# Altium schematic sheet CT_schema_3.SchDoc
size 339 x 183 mm
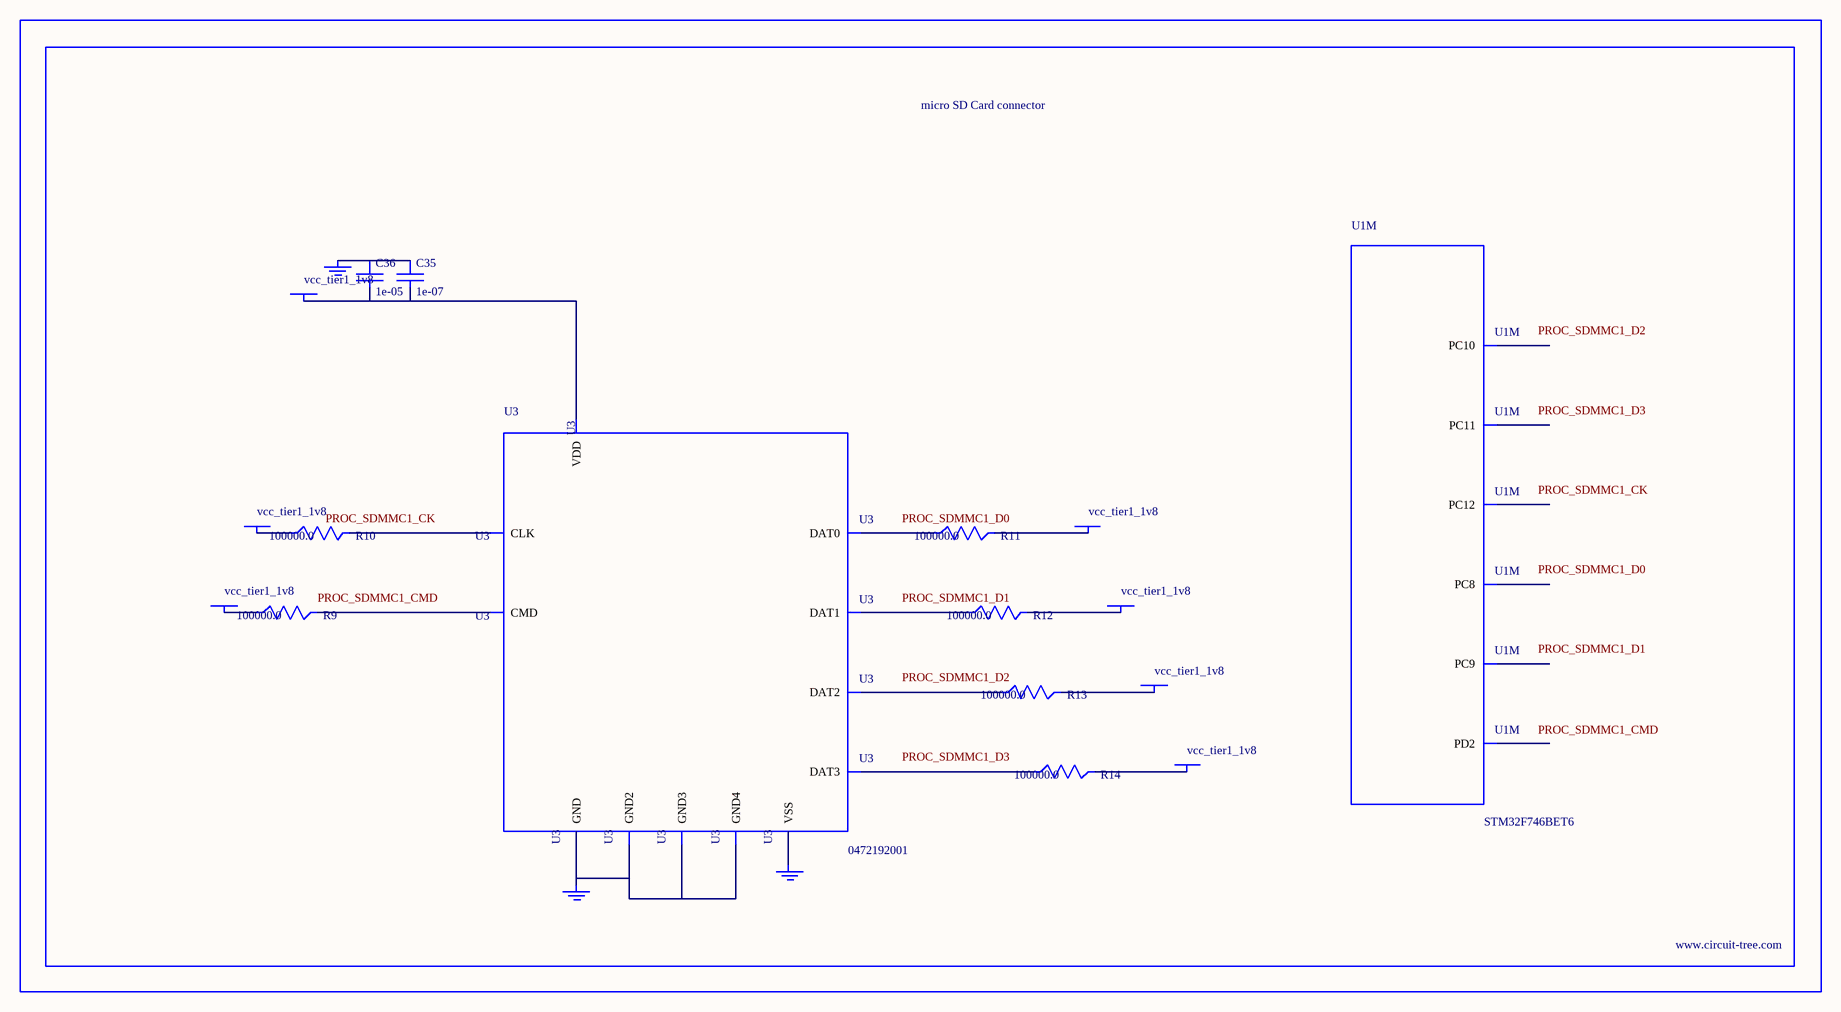
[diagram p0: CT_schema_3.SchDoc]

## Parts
BORDER2  (no value)
C35  1e-07  [C0402]
C36  1e-05  [C0805]
GND_INSTANCE_2_0  (no value)
GND_INSTANCE_2_1  (no value)
GND_INSTANCE_2_2  (no value)
POWER_INSTANCE_2_0  vcc_tier1_1v8
POWER_INSTANCE_2_1  vcc_tier1_1v8
POWER_INSTANCE_2_2  vcc_tier1_1v8
POWER_INSTANCE_2_3  vcc_tier1_1v8
POWER_INSTANCE_2_4  vcc_tier1_1v8
POWER_INSTANCE_2_5  vcc_tier1_1v8
POWER_INSTANCE_2_6  vcc_tier1_1v8
R9  100000.0  [R0603]
R10  100000.0  [R0603]
R11  100000.0  [R0603]
R12  100000.0  [R0603]
R13  100000.0  [R0603]
R14  100000.0  [R0603]
U1  STM32F746BET6  [LQFP208]  (part M of 15)
U3  0472192001  [MOLEX_47219-2001]

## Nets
NetC35_1: C35.1 C36.1 GND_INSTANCE_2_0.0(GND)
NetC35_2: C35.2 C36.2 POWER_INSTANCE_2_3.0(PWR) U3.4(VDD)
NetGND_INSTANCE_2_1_0: GND_INSTANCE_2_1.0(GND) U3.6(VSS)
NetGND_INSTANCE_2_2_0: GND_INSTANCE_2_2.0(GND) U3.G1(GND) U3.G2(GND2) U3.G3(GND3) U3.G4(GND4)
NetPOWER_INSTANCE_2_0_0: POWER_INSTANCE_2_0.0(PWR) R13.2
NetPOWER_INSTANCE_2_1_0: POWER_INSTANCE_2_1.0(PWR) R14.2
NetPOWER_INSTANCE_2_2_0: POWER_INSTANCE_2_2.0(PWR) R9.1
NetPOWER_INSTANCE_2_4_0: POWER_INSTANCE_2_4.0(PWR) R10.1
NetPOWER_INSTANCE_2_5_0: POWER_INSTANCE_2_5.0(PWR) R11.2
NetPOWER_INSTANCE_2_6_0: POWER_INSTANCE_2_6.0(PWR) R12.2
NetR9_2: R9.2 U3.3(CMD)
NetR10_2: R10.2 U3.5(CLK)
NetR11_1: R11.1 U3.7(DAT0)
NetR12_1: R12.1 U3.8(DAT1)
NetR13_1: R13.1 U3.1(DAT2)
NetR14_1: R14.1 U3.2(DAT3)

Not connected (* = marked no-connect by the designer): U1 140(PC8) 141(PC9) 161(PC10) 162(PC11) 163(PC12) 166(PD2)

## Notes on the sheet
- Labels drawn without touching a wire or pin: PROC_SDMMC1_CK, PROC_SDMMC1_CMD, PROC_SDMMC1_D0, PROC_SDMMC1_D1, PROC_SDMMC1_D2, PROC_SDMMC1_D3

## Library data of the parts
BORDER2 = BORDER_PAGE2
C35 = C0402C104K3RACTU
C36 = C0805C106K8RACTU
GND_INSTANCE_2_0-GND_INSTANCE_2_2 = GND
POWER_INSTANCE_2_0-POWER_INSTANCE_2_6 = PWR
R9-R14 = RC0603JR-07100KL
